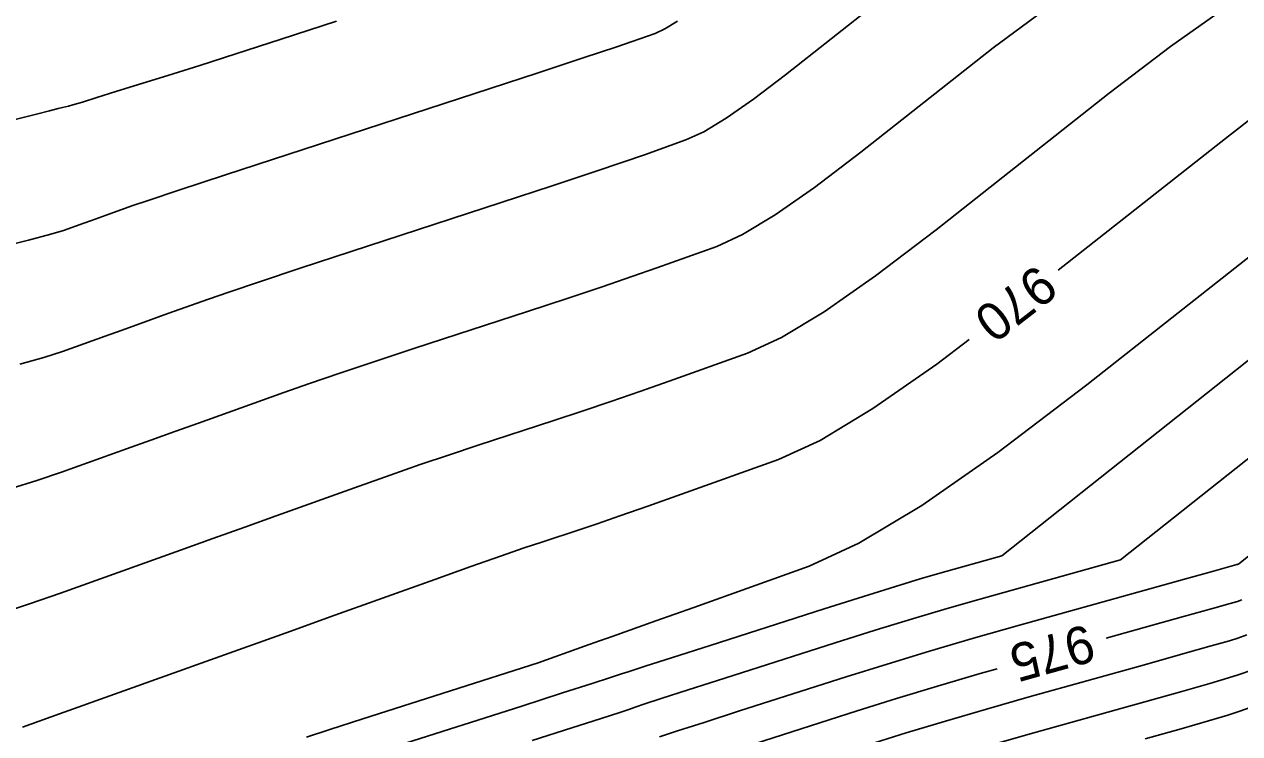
# Model space of a CAD drawing. Extents: x 2175772 to 2185556, y 721391 to 722853.
# Drawn here: x 2178980.9 to 2179071.3, y 721967.6 to 722020.3 of the extents above; entities that cross this region are included whole.
import ezdxf

# ---------------------------------------------------------------- set-up
doc = ezdxf.new("R2010")
doc.units = 0
doc.layers.add('DT_X_Contour_Major', color=7, linetype='Continuous')
doc.layers.add('DT_X_Contour_Minor', color=7, linetype='Continuous')

msp = doc.modelspace()

# ---------------------------------------------------------------- linework, layer by layer
at = {"layer": 'DT_X_Contour_Major'}
for points in [[(2179057.809, 722002.053), (2179070.246, 722011.852), (2179075.635, 722016.04), (2179079.863, 722019.198), (2179082.93, 722021.325), (2179084.835, 722022.421), (2179088.367, 722023.97), (2179089.669, 722024.559), (2179090.927, 722025.166), (2179092.141, 722025.789), (2179093.311, 722026.43), (2179096.371, 722028.161), (2179098.074, 722029.08), (2179100.89, 722030.539), (2179104.817, 722032.538), (2179109.857, 722035.077), (2179124.779, 722042.567), (2179129.865, 722045.062), (2179133.933, 722046.93), (2179136.982, 722048.17), (2179139.013, 722048.783), (2179146.111, 722050.178)], [(2178976.632, 722012.368), (2178981.803, 722013.673), (2178982.773, 722013.916), (2178983.419, 722014.078), (2178983.742, 722014.158), (2178984.171, 722014.26), (2178984.513, 722014.356), (2178985.215, 722014.567), (2178986.278, 722014.894), (2178987.702, 722015.336), (2178991.979, 722016.669), (2178993.941, 722017.289), (2178996.618, 722018.148), (2179000.01, 722019.247), (2179004.118, 722020.586)], [(2178980.756, 721968.095), (2178983.507, 721969.072), (2178991.687, 721972), (2178994.736, 721973.092), (2179000.717, 721975.233), (2179003.65, 721976.283), (2179011.42, 721979.064), (2179014.103, 721980.02), (2179016.325, 721980.803), (2179018.087, 721981.413), (2179019.387, 721981.849), (2179022.24, 721982.781), (2179023.514, 721983.207), (2179025.195, 721983.787), (2179027.285, 721984.52), (2179029.782, 721985.407), (2179036.984, 721987.975), (2179040.093, 721989.406), (2179044.02, 721991.772), (2179048.764, 721995.073), (2179051.171, 721996.906)], [(2179061.361, 721974.694), (2179064.189, 721975.484), (2179067.129, 721976.306), (2179069.267, 721976.906), (2179070.6, 721977.285), (2179071.13, 721977.441), (2179071.471, 721977.564)], [(2179035.206, 721966.852), (2179042.853, 721969.296), (2179045.781, 721970.215), (2179048.826, 721971.138), (2179051.991, 721972.064), (2179053.272, 721972.428)]]:
    msp.add_lwpolyline(points, dxfattribs=at)
at = {"layer": 'DT_X_Contour_Minor'}
for points in [[(2178979.279, 721976.595), (2178981.285, 721977.254), (2178983.582, 721978.057), (2178992.524, 721981.257), (2178994.92, 721982.115), (2178997.287, 721982.963), (2178999.622, 721983.799), (2179005.81, 721986.014), (2179008.103, 721986.826), (2179010.343, 721987.604), (2179012.53, 721988.345), (2179014.664, 721989.051), (2179020.281, 721990.886), (2179022.398, 721991.586), (2179024.534, 721992.308), (2179026.69, 721993.053), (2179028.865, 721993.821), (2179034.692, 721995.899), (2179037.207, 721997.057), (2179040.384, 721998.971), (2179044.223, 722001.642), (2179048.722, 722005.069), (2179061.603, 722015.217), (2179066.147, 722018.686), (2179070.119, 722021.483)], [(2178979.922, 721985.829), (2178981.814, 721986.413), (2178983.657, 721987.041), (2178988.505, 721988.777), (2178990.311, 721989.423), (2178992.095, 721990.062), (2178993.856, 721990.692), (2179000.2, 721992.963), (2179002.103, 721993.632), (2179004.362, 721994.404), (2179006.974, 721995.277), (2179009.94, 721996.253), (2179018.323, 721998.991), (2179021.282, 721999.964), (2179023.872, 722000.829), (2179026.095, 722001.587), (2179027.948, 722002.236), (2179032.4, 722003.823), (2179034.322, 722004.708), (2179036.749, 722006.17), (2179039.681, 722008.21), (2179043.119, 722010.829), (2179052.959, 722018.582), (2179056.658, 722021.332)], [(2178980.565, 721995.063), (2178982.343, 721995.571), (2178983.731, 721996.026), (2178986.913, 721997.165), (2178988.099, 721997.589), (2178989.27, 721998.008), (2178991.567, 721998.831), (2178994.589, 721999.913), (2178996.104, 722000.438), (2178998.38, 722001.204), (2179001.417, 722002.21), (2179005.217, 722003.455), (2179016.364, 722007.097), (2179020.166, 722008.343), (2179023.211, 722009.351), (2179025.5, 722010.12), (2179027.032, 722010.65), (2179030.108, 722011.748), (2179031.436, 722012.359), (2179033.113, 722013.369), (2179035.14, 722014.779), (2179037.516, 722016.589), (2179044.316, 722021.947)], [(2178978.814, 722003.71), (2178981.209, 722004.297), (2178982.872, 722004.73), (2178983.806, 722005.01), (2178985.322, 722005.553), (2178985.887, 722005.755), (2178986.445, 722005.955), (2178986.996, 722006.152), (2178987.539, 722006.346), (2178988.979, 722006.862), (2178990.104, 722007.244), (2178992.398, 722008.004), (2178995.861, 722009.142), (2179000.493, 722010.657), (2179014.405, 722015.202), (2179019.05, 722016.721), (2179022.55, 722017.872), (2179024.905, 722018.653), (2179026.115, 722019.065), (2179027.816, 722019.672), (2179028.551, 722020.01), (2179029.478, 722020.569)], [(2179001.877, 721967.349), (2179003.629, 721967.91), (2179006.077, 721968.693), (2179019.126, 721972.865), (2179022.569, 721974.097), (2179023.692, 721974.499), (2179023.989, 721974.605), (2179024.111, 721974.647), (2179024.199, 721974.676), (2179024.63, 721974.829), (2179027.88, 721975.987), (2179030.698, 721976.992), (2179039.275, 721980.051), (2179042.979, 721981.755), (2179047.655, 721984.572), (2179053.305, 721988.504), (2179059.929, 721993.549), (2179078.889, 722008.487)], [(2179008.702, 721966.715), (2179017.899, 721969.656), (2179020.931, 721970.626), (2179023.128, 721971.33), (2179024.49, 721971.768), (2179025.018, 721971.94), (2179025.312, 721972.045), (2179025.806, 721972.207), (2179027.07, 721972.614), (2179029.103, 721973.265), (2179031.904, 721974.161), (2179040.401, 721976.876), (2179043.317, 721977.802), (2179045.692, 721978.546), (2179047.527, 721979.107), (2179048.822, 721979.484), (2179053.602, 721980.818), (2179076.855, 721999.253)], [(2179028.149, 721967.371), (2179029.475, 721967.802), (2179031.461, 721968.442), (2179034.105, 721969.288), (2179042.036, 721971.823), (2179045.071, 721972.775), (2179048.23, 721973.732), (2179051.512, 721974.693), (2179054.917, 721975.659), (2179064.16, 721978.239), (2179067.194, 721979.086), (2179069.361, 721979.691), (2179071.097, 721980.176), (2179071.103, 721980.178), (2179071.108, 721980.179), (2179071.117, 721980.182), (2179071.131, 721980.186), (2179071.249, 721980.218), (2179087.882, 721993.405)], [(2179018.682, 721967.089), (2179021.628, 721968.032), (2179023.796, 721968.729), (2179025.186, 721969.179), (2179025.799, 721969.382), (2179026.397, 721969.596), (2179026.978, 721969.789), (2179028.273, 721970.208), (2179030.282, 721970.853), (2179033.005, 721971.725), (2179041.218, 721974.349), (2179044.195, 721975.289), (2179046.967, 721976.141), (2179049.533, 721976.904), (2179051.893, 721977.578), (2179062.425, 721980.518), (2179076.408, 721991.603)], [(2179043.671, 721966.77), (2179046.49, 721967.654), (2179049.423, 721968.543), (2179052.471, 721969.435), (2179055.633, 721970.332), (2179064.217, 721972.728), (2179067.065, 721973.526), (2179069.172, 721974.122), (2179070.538, 721974.515), (2179071.163, 721974.707), (2179071.84, 721974.949)], [(2179052.95, 721966.807), (2179055.991, 721967.669), (2179064.245, 721969.973), (2179067.001, 721970.746), (2179069.078, 721971.337), (2179070.476, 721971.746), (2179071.195, 721971.973), (2179072.208, 721972.335)], [(2179064.274, 721967.218), (2179066.937, 721967.966), (2179068.984, 721968.552), (2179070.414, 721968.976), (2179071.228, 721969.238), (2179072.576, 721969.721)]]:
    msp.add_lwpolyline(points, dxfattribs=at)

# ---------------------------------------------------------------- texts
at = {"layer": 'DT_X_Contour_Major'}
for s, rotation, p in [('970', 217.79064, (2179056.265, 722002.587)), ('975', 195.65447, (2179060.005, 721975.773))]:
    msp.add_text(s, height=2.8, rotation=rotation, dxfattribs=at).set_placement(p)

doc.saveas('drawing.dxf')
